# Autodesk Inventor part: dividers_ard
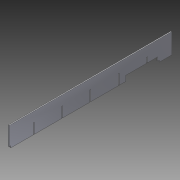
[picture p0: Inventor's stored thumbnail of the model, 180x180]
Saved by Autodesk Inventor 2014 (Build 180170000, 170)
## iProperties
Created: 2014-05
Part Number: dividers_ard
Material: ABS Plastic
Document SubType Name: Modeling
Designer: t_emanb
Density: 1 g/cm^3
Appearance: Smooth - White
Author: t_emanb
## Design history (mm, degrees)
sketch "Sketch1"
  geometry: L1 (0, 0)-(72.39, 0); L2 (72.39, 0)-(72.39, -584.2); L3 (72.39, -584.2)-(0, -584.2); L4 (0, -584.2)-(0, 0); 1 further point
  constraints: 8 end point, 2 parallel, 1 coincident, 1 horizontal, 1 perpendicular
  dimensions: "d0" = 584.2 distance of L1.end L2.end; "d1" = 72.39 distance of L1.start L1.end
extrude "Extrusion1" new body sketch "Sketch1" distance "d2" = 3.048; taper "d3" = 0 deg
sketch "Sketch2" dims "d9" = 25.4, "d18" = 25.4
  geometry: L1 (0, 0)-(584.2, 0) reference; L2 (584.2, 72.39)-(0, 72.39) reference; L3 (88.9, 72.39)-(88.9, 0); L4 (190.5, 72.39)-(190.5, 0); L5 (292.1, 72.39)-(292.1, 0); L6 (393.7, 72.39)-(393.7, 0); L7 (495.3, 72.39)-(495.3, 0); L8 (87.376, 0)-(90.424, 0); L9 (90.424, 0)-(90.424, 38.1); L10 (90.424, 38.1)-(87.376, 38.1); L11 (87.376, 38.1)-(87.376, 0); L12 (188.976, 38.1)-(188.976, 0); L13 (192.024, 38.1)-(188.976, 38.1); L14 (192.024, 0)-(192.024, 38.1); L15 (188.976, 0)-(192.024, 0); L16 (290.576, 38.1)-(290.576, 0); L17 (293.624, 38.1)-(290.576, 38.1); L18 (293.624, 0)-(293.624, 38.1); L19 (290.576, 0)-(293.624, 0); L20 (392.176, 38.1)-(392.176, 0); L21 (395.224, 38.1)-(392.176, 38.1); L22 (395.224, 0)-(395.224, 38.1); L23 (392.176, 0)-(395.224, 0); L24 (493.776, 38.1)-(493.776, 0); L25 (496.824, 38.1)-(493.776, 38.1); L26 (496.824, 0)-(496.824, 38.1); L27 (493.776, 0)-(496.824, 0)
  constraints: 50 end point, 3 horizontal, 3 point on line, 2 parallel, 2 perpendicular, 1 midpoint, 45 other
  dimensions: "d6" = 101.6 distance of L3.start L4.start; "d11" = 3.048 distance of L9.end L10.end; "d12" = 38.1 distance of L10.end L8.start; "d15" = 101.6 distance of L10.end L12.start
extrude "Extrusion2" cut sketch "Sketch2" stored distance "d20" = 3.175; taper "d21" = 0 deg
sketch "Sketch3"
  geometry: L1 (496.824, 0)-(584.2, 0) reference; L2 (584.2, 0)-(584.2, 72.39) reference; L3 (0, 72.39)-(0, 0) reference; L4 (0, 0)-(87.376, 0) reference; L5 (392.176, 0)-(392.176, 38.1) reference; L6 (0, 6.35)-(6.35, 6.35); L7 (6.35, 6.35)-(6.35, 0)
  constraints: 4 end point, 2 perpendicular, 2 point on line
  dimensions: "d26" = 6.35 distance of L6.end L7.end; "d27" = 6.35 distance of L6.start L6.end
extrude "Extrusion3" cut sketch "Sketch3" stored distance "d24" = 25.4; taper "d25" = 0 deg
sketch "Sketch4"
  geometry: L1 (496.824, 0)-(584.2, 0) reference; L2 (584.2, 0)-(584.2, 72.39) reference; L3 (533.4, 0)-(419.1, 0); L4 (419.1, 0)-(419.1, 19.05); L5 (419.1, 19.05)-(533.4, 19.05); L6 (533.4, 19.05)-(533.4, 0); 1 further point
  constraints: 8 end point, 2 parallel, 1 horizontal, 1 perpendicular, 1 point on line
  dimensions: "d28" = 114.3 distance of L4.end L5.end; "d29" = 19.05 distance of L5.end L3.start; "d30" = 50.8 distance between parallel lines of L2 L6
extrude "Extrusion4" cut sketch "Sketch4" stored distance "d31" = 25.4; taper "d32" = 0 deg
sketch "Sketch5"
  geometry: L1 (533.4, 19.05)-(533.4, 0) reference; L2 (533.4, 0)-(584.2, 0) reference; L3 (584.2, 0)-(584.2, 72.39) reference; L4 (395.224, 0)-(419.1, 0) reference; L5 (539.75, 0)-(539.75, 6.35); L6 (539.75, 6.35)-(530.225, 6.35); L7 (530.225, 6.35)-(530.225, 0); L8 (539.75, 0)-(533.4, 0); L9 (533.4, 6.35)-(533.4, 0); 1 further point
  constraints: 10 end point, 4 point on line, 3 perpendicular, 2 collinear
  dimensions: "d33" = 6.35 distance of L6.end L7.end; "d34" = 9.525 distance of L5.end L6.end; "d35" = 44.45 distance between parallel lines of L3 L5
extrude "Extrusion5" cut sketch "Sketch5" stored distance "d36" = 25.4; taper "d37" = 0 deg
body "Solid1"
